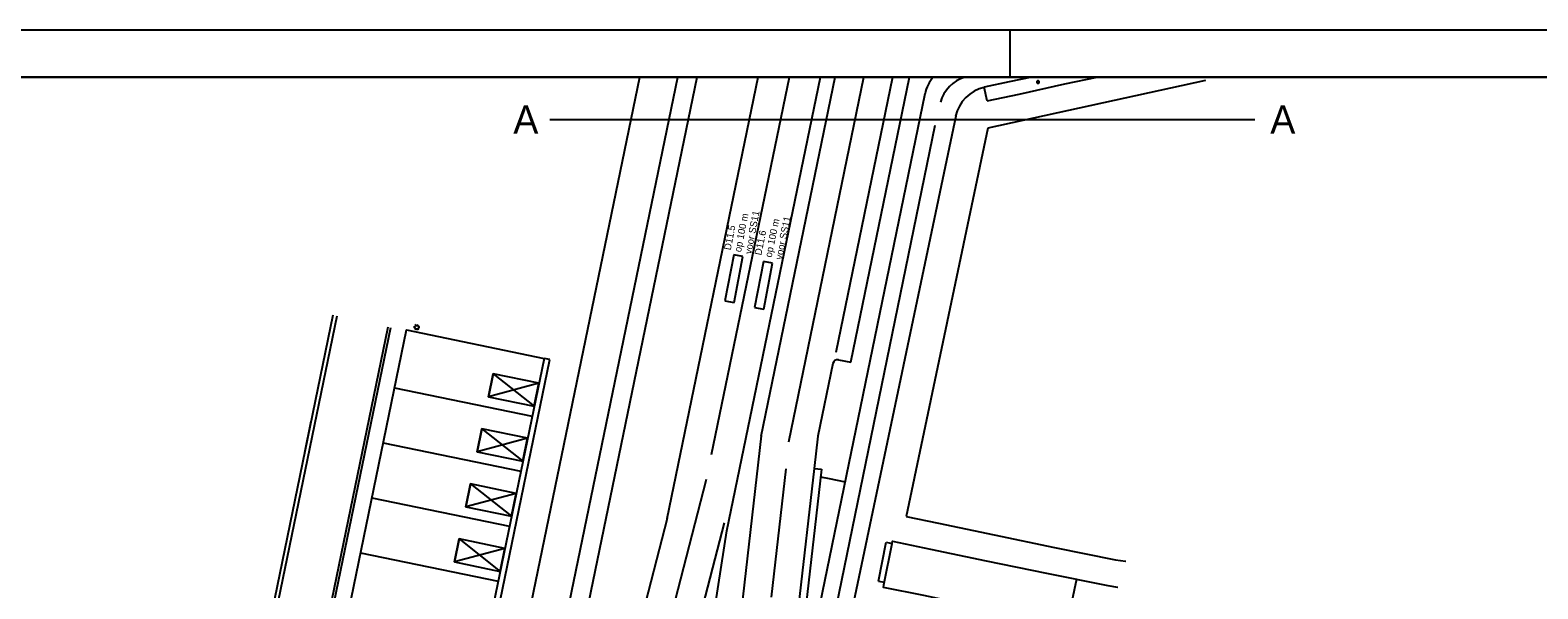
# Model space of a CAD drawing. Extents: x 81065 to 81486, y 452384 to 452681.
# Drawn here: x 81170.8 to 81331.8, y 452620.9 to 452680.5 of the extents above; entities that cross this region are included whole.
import ezdxf

# ---------------------------------------------------------------- set-up
doc = ezdxf.new("R2010")
doc.units = 0
for name, color, linetype in [('B-BH-GK-KADEMUUR-GV', 7, 'Continuous'), ('B-BH-GR-BOOM-S', 7, 'Continuous'), ('B-BH-IE-MEUBILAIR_WEGMEUBILAIR_LICHTMAST-S', 7, 'Continuous'), ('B-BH-OG-TOPOGRAFIE_BEBOUWING-GV', 7, 'Continuous'), ('B-BH-OG-TOPOGRAFIE_BEBOUWING_PANDSCHEIDING-GV', 7, 'Continuous'), ('B-BH-VH-KANTOPSLUITING-GV', 7, 'Continuous'), ('B-WE-VW-MARKERING_LANGS_STREEP_11_010-G', 7, 'Continuous'), ('B-WE-VW-MARKERING_LANGS_STREEP_13_010-G', 7, 'Continuous'), ('B-WE-VW-MARKERING_LANGS_STREEP_13_030-G', 7, 'Continuous'), ('B-WE-VW-MARKERING_LANGS_STREEP_30270_010-G', 7, 'Continuous'), ('N-OI-KL-VRI_LUS_DETECTIE-G', 7, 'Continuous'), ('N-OI-KL-VRI_LUS_DETECTIE-T18', 7, 'Continuous'), ('X-XX-AL-TEKENBLAD_KADER-G', 7, 'Continuous'), ('X-XX-AL-TEKENBLAD_KADER_AFSNIJMARKERING-G', 7, 'Continuous'), ('X-XX-AL-TEKENBLAD_KADER_VOUWMERK-G', 7, 'Continuous'), ('X-XX-AL-TEKENBLAD_VIEWPORT-G', 7, 'Continuous')]:
    doc.layers.add(name, color=color, linetype=linetype)

msp = doc.modelspace()

# ---------------------------------------------------------------- linework, layer by layer
at = {"layer": 'B-BH-GK-KADEMUUR-GV'}
msp.add_line((81200.1, 452635.45), (81200.79, 452638.79), dxfattribs=at)
at = {"layer": 'B-BH-GR-BOOM-S'}
for points in [[(81278.3, 452674.99), (81278.3, 452674.97), (81278.3, 452674.96), (81278.31, 452674.95), (81278.31, 452674.94), (81278.32, 452674.92), (81278.33, 452674.91), (81278.33, 452674.9), (81278.34, 452674.89), (81278.35, 452674.88), (81278.37, 452674.88), (81278.38, 452674.87), (81278.39, 452674.87), (81278.4, 452674.86), (81278.42, 452674.86), (81278.43, 452674.86), (81278.44, 452674.86), (81278.46, 452674.86), (81278.47, 452674.87), (81278.48, 452674.87), (81278.49, 452674.88), (81278.51, 452674.88), (81278.52, 452674.89), (81278.53, 452674.9), (81278.53, 452674.91), (81278.54, 452674.92), (81278.55, 452674.94), (81278.55, 452674.95), (81278.56, 452674.96), (81278.56, 452674.97), (81278.56, 452674.99), (81278.56, 452675), (81278.56, 452675.01), (81278.55, 452675.03), (81278.55, 452675.04), (81278.54, 452675.05), (81278.53, 452675.06), (81278.53, 452675.07), (81278.52, 452675.08), (81278.51, 452675.09), (81278.49, 452675.1), (81278.48, 452675.11), (81278.47, 452675.11), (81278.46, 452675.11), (81278.44, 452675.12), (81278.43, 452675.12), (81278.42, 452675.12), (81278.4, 452675.11), (81278.39, 452675.11), (81278.38, 452675.11), (81278.37, 452675.1), (81278.35, 452675.09), (81278.34, 452675.08), (81278.33, 452675.07), (81278.33, 452675.06), (81278.32, 452675.05), (81278.31, 452675.04), (81278.31, 452675.03), (81278.3, 452675.01), (81278.3, 452675), (81278.3, 452674.99)], [(81278.33, 452674.99), (81278.33, 452674.98), (81278.33, 452674.97), (81278.33, 452674.96), (81278.33, 452674.95), (81278.34, 452674.94), (81278.35, 452674.93), (81278.35, 452674.92), (81278.36, 452674.91), (81278.37, 452674.9), (81278.38, 452674.9), (81278.39, 452674.89), (81278.4, 452674.89), (81278.41, 452674.89), (81278.42, 452674.88), (81278.43, 452674.88), (81278.44, 452674.88), (81278.45, 452674.89), (81278.46, 452674.89), (81278.47, 452674.89), (81278.48, 452674.9), (81278.49, 452674.9), (81278.5, 452674.91), (81278.51, 452674.92), (81278.51, 452674.93), (81278.52, 452674.94), (81278.53, 452674.95), (81278.53, 452674.96), (81278.53, 452674.97), (81278.53, 452674.98), (81278.53, 452674.99), (81278.53, 452675), (81278.53, 452675.01), (81278.53, 452675.02), (81278.53, 452675.03), (81278.52, 452675.04), (81278.51, 452675.05), (81278.51, 452675.06), (81278.5, 452675.07), (81278.49, 452675.07), (81278.48, 452675.08), (81278.47, 452675.08), (81278.46, 452675.09), (81278.45, 452675.09), (81278.44, 452675.09), (81278.43, 452675.09), (81278.42, 452675.09), (81278.41, 452675.09), (81278.4, 452675.09), (81278.39, 452675.08), (81278.38, 452675.08), (81278.37, 452675.07), (81278.36, 452675.07), (81278.35, 452675.06), (81278.35, 452675.05), (81278.34, 452675.04), (81278.33, 452675.03), (81278.33, 452675.02), (81278.33, 452675.01), (81278.33, 452675), (81278.33, 452674.99)], [(81278.35, 452674.99), (81278.35, 452674.98), (81278.35, 452674.97), (81278.35, 452674.96), (81278.36, 452674.95), (81278.36, 452674.95), (81278.36, 452674.94), (81278.37, 452674.93), (81278.38, 452674.93), (81278.38, 452674.92), (81278.39, 452674.92), (81278.4, 452674.91), (81278.4, 452674.91), (81278.41, 452674.91), (81278.42, 452674.91), (81278.43, 452674.91), (81278.44, 452674.91), (81278.45, 452674.91), (81278.46, 452674.91), (81278.46, 452674.91), (81278.47, 452674.92), (81278.48, 452674.92), (81278.48, 452674.93), (81278.49, 452674.93), (81278.5, 452674.94), (81278.5, 452674.95), (81278.5, 452674.95), (81278.51, 452674.96), (81278.51, 452674.97), (81278.51, 452674.98), (81278.51, 452674.99), (81278.51, 452675), (81278.51, 452675), (81278.51, 452675.01), (81278.5, 452675.02), (81278.5, 452675.03), (81278.5, 452675.04), (81278.49, 452675.04), (81278.48, 452675.05), (81278.48, 452675.05), (81278.47, 452675.06), (81278.46, 452675.06), (81278.46, 452675.07), (81278.45, 452675.07), (81278.44, 452675.07), (81278.43, 452675.07), (81278.42, 452675.07), (81278.41, 452675.07), (81278.4, 452675.07), (81278.4, 452675.06), (81278.39, 452675.06), (81278.38, 452675.05), (81278.38, 452675.05), (81278.37, 452675.04), (81278.36, 452675.04), (81278.36, 452675.03), (81278.36, 452675.02), (81278.35, 452675.01), (81278.35, 452675), (81278.35, 452675), (81278.35, 452674.99)], [(81278.37, 452674.99), (81278.37, 452674.98), (81278.37, 452674.98), (81278.37, 452674.97), (81278.38, 452674.96), (81278.38, 452674.96), (81278.38, 452674.95), (81278.39, 452674.95), (81278.39, 452674.94), (81278.4, 452674.94), (81278.4, 452674.94), (81278.41, 452674.93), (81278.41, 452674.93), (81278.42, 452674.93), (81278.42, 452674.93), (81278.43, 452674.93), (81278.44, 452674.93), (81278.44, 452674.93), (81278.45, 452674.93), (81278.45, 452674.93), (81278.46, 452674.94), (81278.46, 452674.94), (81278.47, 452674.94), (81278.47, 452674.95), (81278.48, 452674.95), (81278.48, 452674.96), (81278.48, 452674.96), (81278.49, 452674.97), (81278.49, 452674.98), (81278.49, 452674.98), (81278.49, 452674.99), (81278.49, 452674.99), (81278.49, 452675), (81278.49, 452675.01), (81278.48, 452675.01), (81278.48, 452675.02), (81278.48, 452675.02), (81278.47, 452675.03), (81278.47, 452675.03), (81278.46, 452675.04), (81278.46, 452675.04), (81278.45, 452675.04), (81278.45, 452675.04), (81278.44, 452675.05), (81278.44, 452675.05), (81278.43, 452675.05), (81278.42, 452675.05), (81278.42, 452675.05), (81278.41, 452675.04), (81278.41, 452675.04), (81278.4, 452675.04), (81278.4, 452675.04), (81278.39, 452675.03), (81278.39, 452675.03), (81278.38, 452675.02), (81278.38, 452675.02), (81278.38, 452675.01), (81278.37, 452675.01), (81278.37, 452675), (81278.37, 452674.99), (81278.37, 452674.99)], [(81278.39, 452674.99), (81278.39, 452674.98), (81278.39, 452674.98), (81278.4, 452674.98), (81278.4, 452674.97), (81278.4, 452674.97), (81278.4, 452674.97), (81278.4, 452674.96), (81278.41, 452674.96), (81278.41, 452674.96), (81278.41, 452674.96), (81278.42, 452674.96), (81278.42, 452674.95), (81278.42, 452674.95), (81278.43, 452674.95), (81278.43, 452674.95), (81278.43, 452674.95), (81278.44, 452674.95), (81278.44, 452674.95), (81278.44, 452674.96), (81278.45, 452674.96), (81278.45, 452674.96), (81278.45, 452674.96), (81278.46, 452674.96), (81278.46, 452674.97), (81278.46, 452674.97), (81278.46, 452674.97), (81278.46, 452674.98), (81278.46, 452674.98), (81278.47, 452674.98), (81278.47, 452674.99), (81278.47, 452674.99), (81278.46, 452675), (81278.46, 452675), (81278.46, 452675), (81278.46, 452675.01), (81278.46, 452675.01), (81278.46, 452675.01), (81278.45, 452675.01), (81278.45, 452675.02), (81278.45, 452675.02), (81278.44, 452675.02), (81278.44, 452675.02), (81278.44, 452675.02), (81278.43, 452675.02), (81278.43, 452675.02), (81278.43, 452675.02), (81278.42, 452675.02), (81278.42, 452675.02), (81278.42, 452675.02), (81278.41, 452675.02), (81278.41, 452675.02), (81278.41, 452675.01), (81278.4, 452675.01), (81278.4, 452675.01), (81278.4, 452675.01), (81278.4, 452675), (81278.4, 452675), (81278.39, 452675), (81278.39, 452674.99), (81278.39, 452674.99)], [(81278.42, 452674.99), (81278.42, 452674.99), (81278.42, 452674.99), (81278.42, 452674.98), (81278.42, 452674.98), (81278.42, 452674.98), (81278.42, 452674.98), (81278.42, 452674.98), (81278.42, 452674.98), (81278.42, 452674.98), (81278.42, 452674.98), (81278.42, 452674.98), (81278.43, 452674.98), (81278.43, 452674.98), (81278.43, 452674.98), (81278.43, 452674.98), (81278.43, 452674.98), (81278.43, 452674.98), (81278.43, 452674.98), (81278.44, 452674.98), (81278.44, 452674.98), (81278.44, 452674.98), (81278.44, 452674.98), (81278.44, 452674.98), (81278.44, 452674.98), (81278.44, 452674.98), (81278.44, 452674.98), (81278.44, 452674.98), (81278.44, 452674.99), (81278.44, 452674.99), (81278.44, 452674.99), (81278.44, 452674.99), (81278.44, 452674.99), (81278.44, 452674.99), (81278.44, 452674.99), (81278.44, 452674.99), (81278.44, 452675), (81278.44, 452675), (81278.44, 452675), (81278.44, 452675), (81278.44, 452675), (81278.44, 452675), (81278.43, 452675), (81278.43, 452675), (81278.43, 452675), (81278.43, 452675), (81278.43, 452675), (81278.43, 452675), (81278.43, 452675), (81278.42, 452675), (81278.42, 452675), (81278.42, 452675), (81278.42, 452675), (81278.42, 452675), (81278.42, 452675), (81278.42, 452674.99), (81278.42, 452674.99), (81278.42, 452674.99), (81278.42, 452674.99), (81278.42, 452674.99), (81278.42, 452674.99)]]:
    msp.add_lwpolyline(points, dxfattribs=at)
at = {"layer": 'B-BH-IE-MEUBILAIR_WEGMEUBILAIR_LICHTMAST-S'}
for p, q in [((81211.95, 452648.99), (81211.87, 452649.12)), ((81212.15, 452648.99), (81212.22, 452649.12)), ((81211.85, 452648.81), (81211.7, 452648.81)), ((81211.95, 452648.64), (81211.87, 452648.51)), ((81212.15, 452648.64), (81212.22, 452648.51)), ((81212.25, 452648.81), (81212.4, 452648.81))]:
    msp.add_line(p, q, dxfattribs=at)
msp.add_circle((81212.05, 452648.81), 0.2, dxfattribs=at)
at = {"layer": 'B-BH-OG-TOPOGRAFIE_BEBOUWING-GV'}
msp.add_lwpolyline([(81202.36, 452606.8), (81210.97, 452648.52), (81225.66, 452645.49), (81217.05, 452603.77)], close=True, dxfattribs=at)
at = {"layer": 'B-BH-OG-TOPOGRAFIE_BEBOUWING_PANDSCHEIDING-GV'}
for p, q in [((81209.69, 452642.35), (81224.38, 452639.32)), ((81208.48, 452636.48), (81223.17, 452633.45)), ((81207.27, 452630.6), (81221.96, 452627.57)), ((81206.06, 452624.73), (81220.75, 452621.69))]:
    msp.add_line(p, q, dxfattribs=at)
for points in [[(81224.6, 452640.38), (81225.11, 452642.83), (81220.21, 452643.84), (81219.71, 452641.39)], [(81220.21, 452643.84), (81224.6, 452640.38), (81225.11, 452642.83), (81219.71, 452641.39)], [(81223.39, 452634.51), (81223.9, 452636.96), (81219, 452637.97), (81218.49, 452635.52)], [(81219, 452637.97), (81223.39, 452634.51), (81223.9, 452636.96), (81218.49, 452635.52)], [(81222.18, 452628.63), (81222.68, 452631.08), (81217.79, 452632.09), (81217.28, 452629.64)], [(81217.79, 452632.09), (81222.18, 452628.63), (81222.68, 452631.08), (81217.28, 452629.64)], [(81216.57, 452626.21), (81220.97, 452622.75), (81221.47, 452625.2), (81216.07, 452623.77)], [(81220.97, 452622.75), (81221.47, 452625.2), (81216.57, 452626.21), (81216.07, 452623.77)]]:
    msp.add_lwpolyline(points, close=True, dxfattribs=at)
at = {"layer": 'B-BH-VH-KANTOPSLUITING-GV'}
for p, q in [((81215, 452574.38), (81235.87, 452675.53)), ((81227.42, 452614.8), (81239.95, 452675.53)), ((81229.38, 452614.4), (81242, 452675.53)), ((81238.81, 452628.38), (81248.54, 452675.53)), ((81245.17, 452627.07), (81255.17, 452675.53)), ((81248.85, 452637.18), (81256.77, 452675.53)), ((81258.44, 452645.07), (81264.71, 452675.53)), ((81273, 452672.99), (81272.69, 452674.43)), ((81188.43, 452578.89), (81203.13, 452650.14)), ((81188.77, 452578.37), (81203.56, 452650.04)), ((81194.32, 452577.73), (81208.99, 452648.85)), ((81194.67, 452577.96), (81209.29, 452648.79)), ((81220.96, 452619.61), (81226.27, 452645.37)), ((81226.27, 452645.37), (81225.66, 452645.49)), ((81256.52, 452644.94), (81254.9, 452637.2)), ((81257.1, 452645.33), (81258.44, 452645.07)), ((81248.86, 452637.22), (81246.7, 452618.46)), ((81254.9, 452637.2), (81254.5, 452633.75)), ((81254.5, 452633.75), (81252.82, 452619.14)), ((81255.3, 452633.66), (81253.61, 452619.05)), ((81254.5, 452633.75), (81255.3, 452633.66)), ((81238.81, 452628.38), (81232.53, 452604.15)), ((81241.35, 452602.33), (81245.17, 452627.07)), ((81261.38, 452621.72), (81262.22, 452625.85)), ((81261.95, 452621.3), (81262.86, 452625.73)), ((81262.22, 452625.85), (81262.85, 452625.72)), ((81261.38, 452621.72), (81262.01, 452621.59)), ((81282.55, 452621.9), (81281.47, 452616.9))]:
    msp.add_line(p, q, dxfattribs=at)
for points in [[(81277.75, 452675.53), (81275.35, 452675.01), (81272.69, 452674.43)], [(81273, 452672.99), (81276.42, 452673.71), (81281.29, 452674.79), (81284.75, 452675.53)], [(81296.32, 452675.16), (81273.06, 452670.07)], [(81266.35, 452673.75), (81254.63, 452616.84), (81254.63, 452616.79)], [(81269.63, 452671.35), (81258.27, 452617.41), (81258.27, 452617.36)], [(81273.06, 452670.07), (81264.34, 452628.62)], [(81255.2, 452632.85), (81256.13, 452632.66), (81257.82, 452632.31)], [(81264.34, 452628.62), (81267.78, 452627.89), (81273.74, 452626.65), (81280.18, 452625.31), (81286.72, 452623.99), (81287.78, 452623.84), (81287.82, 452623.85)], [(81262.86, 452625.73), (81262.89, 452625.98), (81266.93, 452625.12), (81272.89, 452623.88), (81279.33, 452622.55), (81285.87, 452621.23), (81286.93, 452621.08), (81286.97, 452621.08)], [(81287.31, 452605.08), (81287.78, 452607.4), (81287.83, 452608.49), (81287.73, 452609.51), (81287.52, 452610.51), (81287.2, 452611.47), (81286.78, 452612.4), (81286.26, 452613.27), (81285.64, 452614.09), (81284.94, 452614.83), (81284.16, 452615.48), (81283.32, 452616.05), (81282.42, 452616.53), (81281.47, 452616.9), (81266.22, 452620.16), (81261.91, 452621.02), (81261.95, 452621.3)]]:
    msp.add_lwpolyline(points, dxfattribs=at)
for centre, radius, start, end in [((81270.27, 452672.93), 4, 139.3963, 168.1103), ((81273.54, 452670.52), 4, 102.3142, 168.1103), ((81257.01, 452644.84), 0.5, 79.121, 168.178)]:
    msp.add_arc(centre, radius, start, end, dxfattribs=at)
at = {"layer": 'B-WE-VW-MARKERING_LANGS_STREEP_11_010-G'}
msp.add_line((81262.89, 452675.53), (81256.83, 452646.13), dxfattribs=at)
at = {"layer": 'B-WE-VW-MARKERING_LANGS_STREEP_13_010-G'}
for p, q in [((81243.54, 452635.22), (81251.86, 452675.53)), ((81251.79, 452636.57), (81259.83, 452675.53)), ((81251.48, 452633.71), (81249.9, 452619.99)), ((81242.99, 452632.55), (81235.45, 452603.47))]:
    msp.add_line(p, q, dxfattribs=at)
at = {"layer": 'B-WE-VW-MARKERING_LANGS_STREEP_13_030-G'}
msp.add_line((81244.89, 452627.94), (81238.38, 452602.79), dxfattribs=at)
at = {"layer": 'B-WE-VW-MARKERING_LANGS_STREEP_30270_010-G'}
msp.add_lwpolyline([(81267.41, 452670.36), (81256.57, 452617.61), (81256.57, 452617.56)], dxfattribs=at)
msp.add_arc((81271.84, 452671.73), 4, 108.1263, 164.0445, dxfattribs=at)
at = {"layer": 'N-OI-KL-VRI_LUS_DETECTIE-G'}
for p, q in [((81245.92, 452656.53), (81244.97, 452651.63)), ((81246.9, 452656.35), (81245.92, 452656.53)), ((81245.95, 452651.44), (81246.9, 452656.35)), ((81249.09, 452655.84), (81248.14, 452650.93)), ((81250.07, 452655.65), (81249.09, 452655.84)), ((81249.12, 452650.74), (81250.07, 452655.65)), ((81244.97, 452651.63), (81245.95, 452651.44)), ((81248.14, 452650.93), (81249.12, 452650.74))]:
    msp.add_line(p, q, dxfattribs=at)
at = {"layer": 'X-XX-AL-TEKENBLAD_KADER-G'}
msp.add_line((81226.27, 452670.98), (81301.6, 452670.98), dxfattribs=at)
msp.add_lwpolyline([(81480.71, 452388.53), (81070.22, 452388.53), (81070.22, 452675.53), (81480.71, 452675.53)], close=True, dxfattribs=at)
at = {"layer": 'X-XX-AL-TEKENBLAD_KADER_AFSNIJMARKERING-G'}
msp.add_lwpolyline([(81485.71, 452680.53), (81065.21, 452680.53), (81065.21, 452383.53), (81485.71, 452383.53)], close=True, dxfattribs=at)
at = {"layer": 'X-XX-AL-TEKENBLAD_KADER_VOUWMERK-G'}
msp.add_line((81275.46, 452675.53), (81275.46, 452680.53), dxfattribs=at)
at = {"layer": 'X-XX-AL-TEKENBLAD_VIEWPORT-G'}
msp.add_lwpolyline([(81070.22, 452388.53), (81480.71, 452388.53), (81480.71, 452675.53), (81070.22, 452675.53)], close=True, dxfattribs=at)

# ---------------------------------------------------------------- texts
at = {"layer": 'N-OI-KL-VRI_LUS_DETECTIE-T18'}
for s, rotation, p in [('op 100 m', 79.0242, (81246.7, 452656.79)), ('voor SS11', 79.0242, (81247.8, 452656.58)), ('op 100 m', 78.2522, (81249.96, 452656.22)), ('voor SS11', 78.2522, (81251.07, 452655.99)), ('D11.5', 79.0242, (81245.6, 452657)), ('D11.6', 78.2522, (81248.86, 452656.45))]:
    msp.add_text(s, height=0.75, rotation=rotation, dxfattribs=at).set_placement(p)
at = {"layer": 'X-XX-AL-TEKENBLAD_KADER-G'}
for p in [(81222.37, 452669.49), (81303.24, 452669.49)]:
    msp.add_text('A', height=3, rotation=0.1528, dxfattribs=at).set_placement(p)

doc.saveas('drawing.dxf')
